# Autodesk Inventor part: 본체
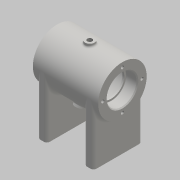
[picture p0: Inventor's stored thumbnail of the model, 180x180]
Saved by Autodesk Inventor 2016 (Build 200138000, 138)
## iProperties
Created: 2020-07
Part Number: 본체
Material: 일반
Document SubType Name: Modeling
Designer: 605-04
Density: 1 g/cm^3
Appearance: 기본값
Mass: 113.055 g
Surface Area: 357.564 cm^2
Volume: 113.055 cm^3
Author: 605-04
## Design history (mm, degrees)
sketch "스케치1"
  geometry: L1 (-35, 0)-(35, 0); L2 (-35, 0)-(-35, 26); L3 (-35, 26)-(35, 26); L4 (35, 26)-(35, 0); L5 (-35, 16)-(-23, 16); L6 (-23, 16)-(-23, 14); L7 (-23, 14)-(-21, 14); L8 (-21, 14)-(-21, 21); L9 (-21, 21)-(21, 21); L10 (21, 21)-(21, 14); L11 (21, 14)-(23, 14); L12 (23, 14)-(23, 16); L13 (23, 16)-(35, 16); 2 further points
  constraints: 26 end point, 10 perpendicular, 2 horizontal, 2 point on line, 1 coincident, 1 midpoint, 1 vertical
  dimensions: "d0" = 70 distance of L1.start L1.end; "d1" = 52 diameter of L3 L1; "d2" = 12 distance between parallel lines of L6 L2; "d3" = 42 distance between parallel lines of L10 L8; "d4" = 12 distance between parallel lines of L4 L12; "d5" = 2 distance of L6.end L7.end; "d6" = 32 diameter of L5 L1; "d7" = 28 diameter of L7 L1; "d8" = 42 diameter of L9 L1; "d9" = 28 diameter of L11 L1; "d10" = 32 diameter of L13 L1
revolve "회전1" sketch "스케치1" stored, may be unused: angle "d11" = 90 deg
node "작업 평면1"
sketch "스케치2"
  geometry: L1 (-35, -26)-(-35, 26) reference; L2 (35, -26)-(35, 26) reference; L3 (-35, 26)-(35, 26) reference; L4 (-35, -26)-(35, -26) reference; L5 (20, 26)-(30, 26); L6 (30, 26)-(30, -26); L7 (30, -26)-(20, -26); L8 (20, -26)-(20, 26); L9 (20, 26)-(30, -26); L10 (30, 26)-(20, -26); L11 (-30, 26)-(-20, 26); L12 (-20, 26)-(-20, -26); L13 (-20, -26)-(-30, -26); L14 (-30, -26)-(-30, 26); L15 (-30, 26)-(-20, -26); L16 (-20, 26)-(-30, -26); 5 further points
  constraints: 24 end point, 6 midpoint, 4 parallel, 2 horizontal, 2 horizontal alignment, 2 perpendicular
  dimensions: "d14" = 52 distance of L5.end L6.end; "d15" = 10 distance between parallel lines of L6 L8; "d17" = 10 distance of L11.start L11.end; "d18" = 52 distance of L13.end L11.start; "d19" = 20 distance from line of L12 point (0, 0); "d20" = 20 distance from line of L8 point (0, 0)
extrude "돌출1" join sketch "스케치2" stored distance "d21" = 10; taper "d22" = 0 deg
node "작업 평면2"
sketch "스케치3"
  geometry: L1 (20, 26)-(20, -26) reference; L2 (20, -26)-(30, -26) reference; L3 (30, -26)-(30, 26) reference; L4 (20, 26)-(30, 26) reference; L5 (-30, -26)-(-20, -26) reference; L6 (-20, -26)-(-20, 26) reference; L7 (-30, 26)-(-20, 26) reference; L8 (-30, 26)-(-30, -26) reference; L9 (-35, -26)-(-35, 26) reference; L10 (35, -26)-(35, 26) reference; C1 r 5 at (0, 0); 1 further point
  constraints: 1 centre point, 1 coincident
  dimensions: "d24" = 10 diameter of C1
extrude "돌출2" join sketch "스케치3" stored distance "d25" = 10; taper "d26" = 0 deg
sketch "스케치4"
  geometry: C1 r 5 at (0, 0) reference; 1 further point
hole "구멍1" sketch "스케치4" at (0, 0) diameter "d27" = 5.188; stored, may be unused: countersink angle "d31" = 90 deg, drill point angle "d33" = 118 deg; dims "d28" = 12, "d29" = 4, "d30" = 2, "d32" = 16
sketch "스케치5"
  geometry: L1 (0, 0)-(0, -26.162); L2 (0, 0)-(-9.919, -27.251); L3 (-15.557, -25.199)-(-13.505, -19.561); L4 (-15.557, -25.199)-(-9.919, -27.251); L5 (-13.505, -19.561)-(-7.866, -21.613)
  constraints: 10 end point, 2 perpendicular, 1 point on line, 1 vertical
  dimensions: "d34" = 29 distance of L1.start L2.end; "d35" = 20 deg angle of L1 L2; "d36" = 6 distance between parallel lines of L2 L3; "d37" = 6 distance between parallel lines of L4 L5
revolve "회전2" sketch "스케치5" stored, may be unused: angle "d38" = 90 deg
sketch "스케치6"
  geometry: C1 r 6 at (0, 0) reference; 1 further point
hole "구멍2" sketch "스케치6" at (0, 0) diameter "d39" = 5.188; stored, may be unused: countersink angle "d43" = 90 deg, drill point angle "d45" = 118 deg; dims "d40" = 12, "d41" = 4, "d42" = 2, "d44" = 16
sketch "스케치7"
  geometry: L1 (30, 26)-(20, 26) reference; L2 (20, 26)-(20, -26) reference; L3 (20, -26)-(30, -26) reference; L4 (30, -26)-(30, 26) reference; L5 (-20, 26)-(-30, 26) reference; L6 (-30, 26)-(-30, -26) reference; L7 (-30, -26)-(-20, -26) reference; L8 (-20, -26)-(-20, 26) reference; L9 (-25, 20)-(25, 20); L10 (25, 20)-(25, -20); L11 (25, -20)-(-25, -20); L12 (-25, -20)-(-25, 20); L13 (-25, 20)-(25, -20); L14 (25, 20)-(-25, -20); C1 r 5 at (0, 0) reference; 1 further point
  constraints: 12 end point, 2 midpoint, 2 parallel, 1 horizontal, 1 perpendicular
  dimensions: "d46" = 40 distance of L9.end L10.end; "d47" = 50 distance of L10.end L11.end
hole "구멍3" sketch "스케치7" at (25, 20), (25, -20), (-25, -20), (-25, 20) diameter "d48" = 4.134; stored, may be unused: countersink angle "d52" = 90 deg, drill point angle "d54" = 118 deg; dims "d49" = 8, "d50" = 4, "d51" = 2, "d53" = 10
sketch "스케치8"
  geometry: L1 (0, 0)-(-21, 0)
  constraints: 2 end point, 1 horizontal
  dimensions: "d55" = 21 distance of L1.start L1.end
hole "구멍4" sketch "스케치8" at (-21, 0) diameter "d56" = 3.242; stored, may be unused: countersink angle "d60" = 90 deg, drill point angle "d62" = 118 deg; dims "d57" = 8, "d58" = 4, "d59" = 2, "d61" = 10
fillet "모깎기1" dims "d66" = 0.3
fillet "모깎기2" dims "d67" = 3
fillet "모깎기3" dims "d68" = 3, "d69" = 2
chamfer "모따기1" distance "d70" = 1; stored, may be unused: second distance "d71" = 2, angle "d72" = 45 deg
node "작업 평면3"
sketch "스케치9"
  geometry: L1 (-35, 26)-(-35, -26) reference; 2 further points
  constraints: 1 other
  dimensions: "d74" = 35 distance from line of L1 point (0, 0); "d75" = 26 vertical distance of L1.start point (0, 0)
feature "엠보싱1" sketch "스케치9" dims "d0" = 70, "d1" = 52, "d2" = 12, "d3" = 42, "d4" = 12, "d5" = 2, "d6" = 32, "d7" = 28, "d8" = 42, "d9" = 28, "d10" = 32, "d76" = 0.5, "d77" = 0
node "솔리드1"
pattern_circular "원형 패턴1" dims angle "d64" = 360 deg
mirror "대칭1"
node "투영된 루프1"
node "투영된 루프2"
node "투영된 루프3"
node "투영된 루프4"
node "투영된 루프5"
node "투영된 루프6"
other parameters: "d12" = -64, "d23" = 29, "d73" = 26
